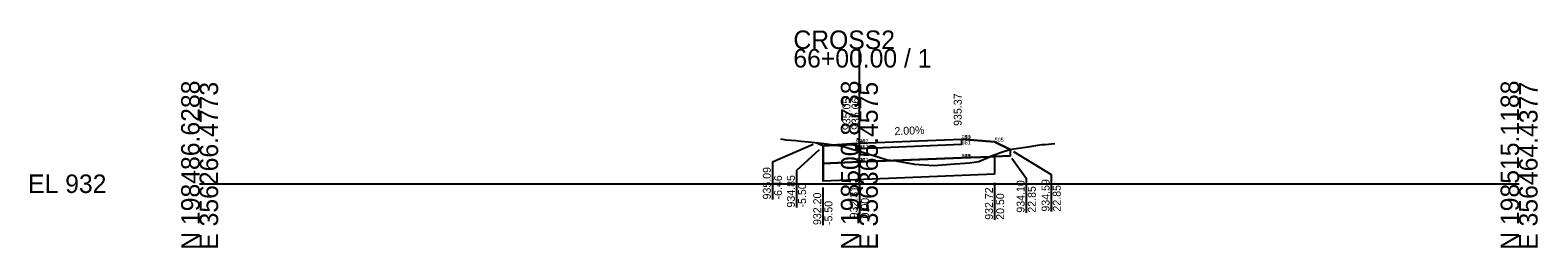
# Model space of a CAD drawing. Extents: x -26 to 203, y -10 to 14021.
# Drawn here: x -25.7 to 202.8, y 6990.3 to 7023.2 of the extents above; entities that cross this region are included whole.
import ezdxf

# ---------------------------------------------------------------- set-up
doc = ezdxf.new("R2010")
doc.units = 0
for name, color, linetype in [('Default', 7, 'Continuous'), ('P_E_XS_Ground', 7, 'Continuous'), ('P_XS', 7, 'Continuous'), ('P_XS_Bold', 7, 'Continuous'), ('P_XS_EAR_CommonGrnd', 7, 'Continuous'), ('P_XS_Lane', 7, 'Continuous'), ('P_XS_Rock', 7, 'Continuous')]:
    doc.layers.add(name, color=color, linetype=linetype)

msp = doc.modelspace()

# ---------------------------------------------------------------- linework, layer by layer
at = {"layer": 'Default'}
for p, q in [((100, 7000), (100, 7020.38)), ((0, 7000), (100, 7000)), ((100, 7000), (200, 7000))]:
    msp.add_line(p, q, dxfattribs=at)
at = {"layer": 'P_E_XS_Ground'}
for p, q in [((88.05, 7006.79), (88.91, 7006.64)), ((88.91, 7006.64), (90.43, 7006.55)), ((90.43, 7006.55), (91.14, 7006.46)), ((91.14, 7006.46), (92.31, 7006.32)), ((92.31, 7006.32), (94.65, 7006.07)), ((94.65, 7006.07), (96.83, 7005.78)), ((96.83, 7005.78), (97.61, 7005.64)), ((97.61, 7005.64), (99.04, 7005.19)), ((99.04, 7005.19), (100, 7004.9)), ((100, 7004.9), (102.97, 7004)), ((120.05, 7004.21), (121.37, 7004.71)), ((121.37, 7004.71), (122.82, 7005.16)), ((122.82, 7005.16), (123.39, 7005.3)), ((123.39, 7005.3), (125.87, 7005.63)), ((125.87, 7005.63), (127.07, 7005.82)), ((127.07, 7005.82), (127.63, 7005.92)), ((127.63, 7005.92), (128.17, 7005.93)), ((128.17, 7005.93), (129.65, 7006.07)), ((102.97, 7004), (104.22, 7003.63)), ((104.22, 7003.63), (105.2, 7003.53)), ((105.2, 7003.53), (108.35, 7002.95)), ((108.35, 7002.95), (110.55, 7002.81)), ((110.55, 7002.81), (111.27, 7002.78)), ((111.27, 7002.78), (111.93, 7002.79)), ((111.93, 7002.79), (113.81, 7002.97)), ((113.81, 7002.97), (116.68, 7003.14)), ((116.68, 7003.14), (118.1, 7003.36)), ((118.1, 7003.36), (120.05, 7004.21))]:
    msp.add_line(p, q, dxfattribs=at)
at = {"layer": 'P_XS'}
for p, q in [((94.5, 7005.71), (94.5, 7003.07)), ((99.5, 7006.11), (99.5, 7005.27)), ((99.5, 7005.27), (100, 7005.29)), ((115.5, 7005.91), (100, 7005.29)), ((115.5, 7006.75), (115.5, 7005.91)), ((122.85, 7005.17), (122.85, 7004.21)), ((94.5, 7003.07), (100, 7003.29)), ((94.5, 7003.07), (94.5, 7000.4)), ((115.5, 7003.91), (100, 7003.29)), ((115.5, 7003.91), (122.85, 7004.21)), ((120.5, 7004.11), (120.5, 7001.44)), ((120.5, 7001.44), (94.5, 7000.4))]:
    msp.add_line(p, q, dxfattribs=at)
at = {"layer": 'P_XS_EAR_CommonGrnd'}
for points in [[(94.65, 7006.07), (96.3, 7005.85), (94.5, 7005.71), (93.54, 7006.19)], [(97.61, 7005.64), (99.04, 7005.19), (100, 7004.9), (102.97, 7004), (104.22, 7003.63), (105.2, 7003.53), (105.35, 7003.51), (100, 7003.29), (94.5, 7003.07), (94.5, 7005.71), (96.3, 7005.85), (96.83, 7005.78)], [(97.61, 7005.64), (99.04, 7005.19), (100, 7004.9), (102.97, 7004), (104.22, 7003.63), (105.2, 7003.53), (105.35, 7003.51), (115.5, 7003.91), (119.76, 7004.08), (120.05, 7004.21), (121.37, 7004.71), (122.82, 7005.16), (122.85, 7005.17), (120.5, 7006.35), (115.5, 7006.75), (115.5, 7005.91), (100, 7005.29), (99.5, 7005.27), (99.5, 7006.11), (96.3, 7005.85), (96.83, 7005.78)], [(99.5, 7006.11), (100, 7006.13), (115.5, 7006.75), (115.5, 7005.91), (100, 7005.29), (99.5, 7005.27)], [(122.82, 7005.16), (122.85, 7005.17), (122.85, 7004.21), (120.5, 7004.11), (119.76, 7004.08), (120.05, 7004.21), (121.37, 7004.71)], [(120.5, 7001.44), (94.5, 7000.4), (94.5, 7003.07), (100, 7003.29), (105.35, 7003.51), (108.35, 7002.95), (110.55, 7002.81), (111.27, 7002.78), (111.93, 7002.79), (113.81, 7002.97), (116.68, 7003.14), (118.1, 7003.36), (119.76, 7004.08), (120.5, 7004.11)], [(105.35, 7003.51), (108.35, 7002.95), (110.55, 7002.81), (111.27, 7002.78), (111.93, 7002.79), (113.81, 7002.97), (116.68, 7003.14), (118.1, 7003.36), (119.76, 7004.08), (115.5, 7003.91)]]:
    msp.add_lwpolyline(points, close=True, dxfattribs=at)
at = {"layer": 'P_XS_Lane'}
for p, q in [((93.54, 7006.19), (94.5, 7005.71)), ((99.5, 7006.11), (94.5, 7005.71)), ((99.5, 7006.11), (100, 7006.13)), ((100, 7006.13), (115.5, 7006.75)), ((115.5, 7006.75), (120.5, 7006.35)), ((120.5, 7006.35), (122.85, 7005.17))]:
    msp.add_line(p, q, dxfattribs=at)
at = {"layer": 'P_XS_Rock'}
for p, q in [((86.82, 7003.31), (93, 7005.96)), ((93.9, 7005.15), (90.47, 7001.99)), ((123.37, 7004.85), (129.07, 7001.38)), ((86.82, 7003.31), (86.82, 6997.62)), ((123.11, 7003.85), (125.29, 7000.82)), ((90.47, 7001.99), (90.47, 6996.4)), ((100, 7000.04), (100, 6994.75)), ((120.49, 7000.14), (120.49, 6994.54)), ((125.29, 7000.82), (125.29, 6995.61)), ((129.07, 7001.38), (129.07, 6995.79)), ((94.46, 6999.45), (94.46, 6993.75))]:
    msp.add_line(p, q, dxfattribs=at)

# ---------------------------------------------------------------- texts
at = {"layer": 'Default'}
for s, p in [('CROSS2', (90, 7020.38)), ('66+00.00 / 1', (90, 7017.58)), ('EL 932', (-26, 6998.6))]:
    msp.add_text(s, height=2.8, dxfattribs=at).set_placement(p)
for s, p in [('N 198486.6288', (0, 6990)), ('E 356266.4773', (2.8, 6990)), ('N 198500.8738', (100, 6990)), ('E 356365.4575', (102.8, 6990)), ('N 198515.1188', (200, 6990)), ('E 356464.4377', (202.8, 6990))]:
    msp.add_text(s, height=2.8, rotation=90, dxfattribs=at).set_placement(p)
at = {"layer": 'P_XS_Bold'}
for s, p in [('951', (115.5, 7006.75)), ('9', (115.5, 7006.75)), ('900', (115.5, 7006.75)), ('910', (115.5, 7006.75)), ('505', (120.5, 7006.35)), ('951', (99.5, 7006.11)), ('9', (99.5, 7006.11)), ('900', (99.5, 7006.11)), ('961', (99.5, 7005.27)), ('952', (100, 7006.13)), ('952', (100, 7006.13)), ('962', (100, 7005.29)), ('962', (100, 7005.29)), ('961', (115.5, 7005.91)), ('971', (99.5, 7003.27)), ('998', (99.5, 7003.27)), ('972', (100, 7003.29)), ('972', (100, 7003.29)), ('540', (115.5, 7003.91)), ('971', (115.5, 7003.91)), ('998', (115.5, 7003.91))]:
    msp.add_text(s, height=0.6, dxfattribs=at).set_placement(p)
at = {"layer": 'P_XS_Rock'}
for s, rotation, p in [('935.05', 90, (98.64, 7008.11)), ('935.06', 90, (100, 7008.13)), ('935.06', 90, (100, 7008.13)), ('935.06', 90, (100, 7008.13)), ('935.06', 90, (100, 7008.13)), ('935.37', 90, (115.5, 7008.75)), ('2.00%', 2.2906, (105.34, 7007.34)), ('935.09', 90, (86.57, 6997.62)), ('-6.46', 90, (88.27, 6997.62)), ('934.85', 90, (90.22, 6996.4)), ('-5.50', 90, (91.92, 6996.4)), ('934.10', 90, (125.04, 6995.62)), ('934.59', 90, (128.82, 6995.79)), ('932.20', 90, (94.21, 6993.75)), ('932.31', 90, (99.75, 6994.75)), ('0.00', 90, (101.45, 6994.75)), ('932.72', 90, (120.24, 6994.54)), ('20.50', 90, (121.94, 6994.54)), ('22.85', 90, (126.74, 6995.62)), ('22.85', 90, (130.52, 6995.79)), ('-5.50', 90, (95.91, 6993.75))]:
    msp.add_text(s, height=1.2, rotation=rotation, dxfattribs=at).set_placement(p)

doc.saveas('drawing.dxf')
